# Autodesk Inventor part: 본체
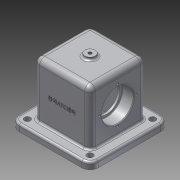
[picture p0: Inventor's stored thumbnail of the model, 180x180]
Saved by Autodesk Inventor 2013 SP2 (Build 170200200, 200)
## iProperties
Created: 2022-07
Part Number: 본체
Material: 알루미늄 6061
Document SubType Name: Modeling
Designer: aa
Density: 2.71 g/cm^3
Mass: 1063.76 g
Surface Area: 721.846 cm^2
Volume: 392.53 cm^3
Author: aa
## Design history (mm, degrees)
sketch "스케치1"
  geometry: L1 (58, -58)-(-58, -58); L2 (-58, -58)-(-58, 58); L3 (-58, 58)-(58, 58); L4 (58, 58)-(58, -58); L5 (58, -58)-(-58, 58); L6 (-58, -58)-(58, 58); 1 further point
  constraints: 12 end point, 2 midpoint, 2 parallel, 1 horizontal, 1 perpendicular
  dimensions: "d0" = 116 distance of L2.end L3.end; "d1" = 116 distance of L1.end L2.end
extrude "돌출1" new body sketch "스케치1" distance "d2" = 10; taper "d3" = 0 deg
sketch "스케치2"
  geometry: L1 (-41, -41)-(41, -41); L2 (41, -41)-(41, 41); L3 (41, 41)-(-41, 41); L4 (-41, 41)-(-41, -41); L5 (-41, -41)-(41, 41); L6 (41, -41)-(-41, 41); 1 further point
  constraints: 12 end point, 2 midpoint, 2 parallel, 1 horizontal, 1 perpendicular
  dimensions: "d4" = 82 distance of L3.end L2.end; "d5" = 82 distance of L2.end L1.end
extrude "돌출2" join sketch "스케치2" distance "d6" = 80; taper "d7" = 0 deg
sketch "스케치3"
  geometry: C1 r 7.5 at (0, 0); 1 further point
  constraints: 1 centre point, 1 coincident
  dimensions: "d8" = 15 diameter of C1
extrude "돌출3" join sketch "스케치3" distance "d9" = 4; taper "d10" = 0 deg
sketch "스케치5"
  geometry: L1 (-21, 30)-(21, 30); L2 (21, 30)-(21, -30); L3 (21, -30)-(-21, -30); L4 (-21, -30)-(-21, 30); L5 (-21, 30)-(21, -30); L6 (21, 30)-(-21, -30); 1 further point
  constraints: 12 end point, 2 midpoint, 2 parallel, 1 horizontal, 1 perpendicular
  dimensions: "d19" = 42 distance of L2.end L3.end; "d20" = 60 distance of L1.end L2.end
extrude "돌출4" cut sketch "스케치5" distance "d21" = 80; taper "d22" = 0 deg
sketch "스케치6"
  geometry: C1 r 7.5 at (0, 0) reference; 1 further point
  constraints: 1 coincident
hole "구멍1" sketch "스케치6" at (0, 0) diameter "d23" = 4.917; stored, may be unused: countersink angle "d27" = 90 deg, drill point angle "d29" = 118 deg; dims "d24" = 20, "d25" = 4, "d26" = 2, "d28" = 22
sketch "스케치7"
  geometry: L1 (0, 0)-(0, 48); L2 (-41, 10)-(-41, 90) reference; L3 (41, 10)-(41, 90) reference; L4 (-41, 48)-(41, 48); L5 (-41, 48)-(-41, 71.5); L6 (-41, 71.5)-(-24, 71.5); L7 (-24, 71.5)-(-24, 68); L8 (-24, 68)-(24, 68); L9 (24, 68)-(24, 71.5); L10 (24, 71.5)-(41, 71.5); L11 (41, 48)-(41, 71.5)
  constraints: 18 end point, 4 perpendicular, 4 point on line, 2 parallel, 1 collinear, 1 vertical
  dimensions: "d30" = 48 distance of L1.start L1.end; "d31" = 47 diameter of L6 L4; "d32" = 40 diameter of L8 L4; "d33" = 17 distance of L5.end L6.end; "d34" = 17 distance of L9.end L10.end; "d35" = 47 diameter of L10 L4; "d36" = 48 vertical distance of L1.start L4.end
revolve "회전1" sketch "스케치7" stored, may be unused: angle "d37" = 90 deg
fillet "모깎기1" dims "d38" = 12
sketch "스케치8"
  geometry: A1 r 12 centre (-46, 46) between (-46, 58) and (-58, 46) reference; A2 r 12 centre (-46, -46) between (-58, -46) and (-46, -58) reference; A3 r 12 centre (46, -46) between (46, -58) and (58, -46) reference; A4 r 12 centre (46, 46) between (58, 46) and (46, 58) reference; 5 further points
  constraints: 4 coincident
hole "구멍2" sketch "스케치8" at (-46, 46), (46, 46), (46, -46), (-46, -46) diameter "d39" = 9; stored, may be unused: countersink angle "d43" = 90 deg, drill point angle "d45" = 118 deg; dims "d40" = 10, "d41" = 4, "d42" = 2, "d44" = 12
sketch "스케치9"
  geometry: C1 r 23.5 at (41, 38) reference; A1 r 27 centre (41, 38) between (41, 65) and (41, 11); 3 further points
  constraints: 4 point on circle, 2 horizontal alignment, 2 vertical alignment, 1 centre point, 1 coincident
  dimensions: "d46" = 54 diameter of A1
hole "구멍3" sketch "스케치9" at (41, 65), (41, 11), (14, 38), (68, 38) diameter "d47" = 3.242; stored, may be unused: countersink angle "d51" = 90 deg, drill point angle "d53" = 118 deg; dims "d48" = 8, "d49" = 4, "d50" = 2, "d52" = 10
fillet "모깎기2" dims "d54" = 3
fillet "모깎기3" dims "d55" = 8
fillet "모깎기4" dims "d56" = 8
fillet "모깎기5" dims "d57" = 3
chamfer "모따기1" distance "d58" = 1; stored, may be unused: second distance "d59" = 2, angle "d60" = 45 deg
fillet "모깎기6" dims "d61" = 3
fillet "모깎기7" dims "d62" = 3
sketch "스케치10"
  geometry: L1 (79, -82)-(-13, -82) reference; 3 further points
  constraints: 1 midpoint, 1 vertical alignment, 1 other
  dimensions: "d63" = 48 distance from line of point (33, -34) L1
feature "엠보싱1" sketch "스케치10" dims "d0" = 116, "d1" = 116, "d64" = 0.5, "d65" = 0
fillet "모깎기8" dims "d66" = 0.6
node "솔리드1"
mirror "대칭1"
